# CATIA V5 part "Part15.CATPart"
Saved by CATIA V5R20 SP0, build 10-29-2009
Part number: 1PCR79791640_ISO 8735-16x40-A-St
Revision: ANY
Definition: UNKNOWN
Nomenclature: 1PCR79791640_ISO 8735-16x40-A-St
Source: Unknown
Bounding box of the stored display mesh (mm): x 0 to 40, y -8 to 8, z -8 to 8
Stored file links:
  C:\Users\Utente\Desktop\IO LAVORO\3D X SITO CF\CUMSA\3D files RC\RC 328016\Part15.CATPart
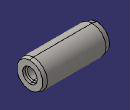
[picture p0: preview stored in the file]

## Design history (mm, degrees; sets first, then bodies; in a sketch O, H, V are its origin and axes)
Body1 "TypeA" (main body)
  Solid1: solid without history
